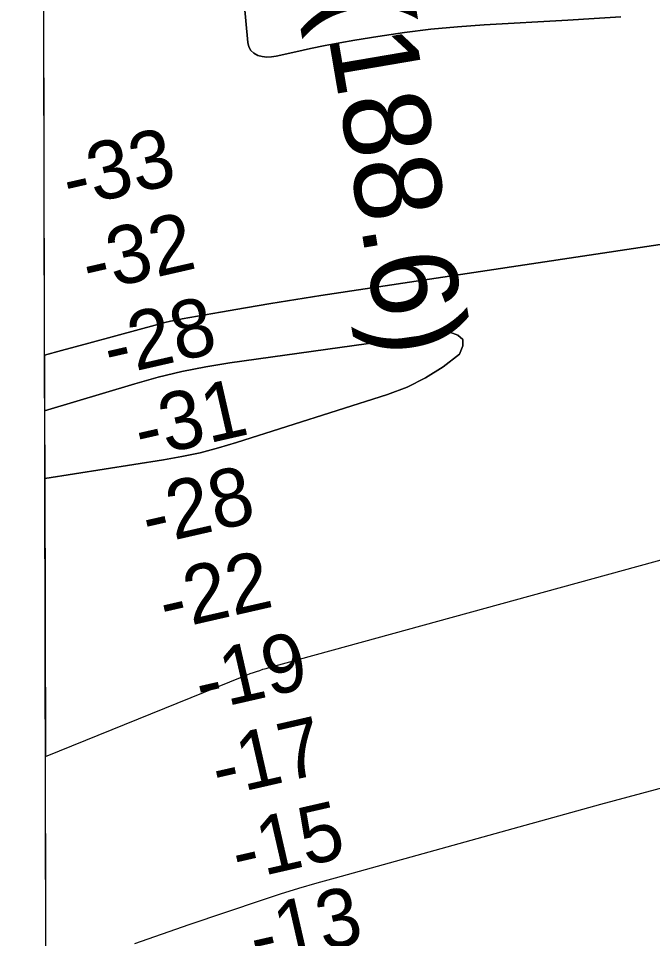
# Model space of a CAD drawing. Extents: x 3355677 to 3393573, y 612928 to 638357.
# Drawn here: x 3359768 to 3360499, y 622036 to 623097 of the extents above; entities that cross this region are included whole.
import ezdxf

# ---------------------------------------------------------------- set-up
doc = ezdxf.new("R2010")
doc.units = 0
for name, color, linetype in [('V-CHAN-NAID', 7, 'Continuous'), ('V-GRID-FRAM', 7, 'Continuous'), ('V-RIVR-RANG', 7, 'Continuous'), ('V-TOPO-DPTH', 7, 'Continuous'), ('V-TOPO-MINR', 7, 'Continuous')]:
    doc.layers.add(name, color=color, linetype=linetype)

msp = doc.modelspace()

# ---------------------------------------------------------------- linework, layer by layer
at = {"layer": 'V-GRID-FRAM'}
msp.add_lwpolyline([(3359767.9, 636495.9), (3391341.6, 636578.5), (3391397.2, 618394.8), (3359807.6, 618312.1), (3359767.9, 636495.9)], dxfattribs=at)
at = {"layer": 'V-TOPO-DPTH'}
for points in [[(3359798, 622708.4), (3359795.6, 623812.8), (3359849.6, 623825), (3359885.2, 623832.8), (3359920.7, 623840.5), (3359956.3, 623848), (3359992, 623855.3), (3360422, 623941.7), (3360433.7, 623944), (3360445.4, 623946.2), (3360457.1, 623948.3), (3360468.8, 623950.4), (3360559.4, 623965.6), (3360616.5, 623975.1), (3360673.6, 623984.5), (3360730.7, 623993.5), (3360787.8, 624002.5), (3361207.2, 624067.1), (3361223.6, 624069.5), (3361240, 624071.9), (3361256.4, 624074), (3361948, 624112.6)], [(3359974.9, 623692), (3360032.3, 623068.8), (3360033.6, 623063.9), (3360035.9, 623059.7), (3360039.4, 623056.6), (3360043.7, 623054.1), (3360049, 623052.8), (3360054.3, 623052), (3360059.6, 623052.2), (3360065, 623053), (3360087.8, 623058.2), (3360104.6, 623061.9), (3360121.5, 623065.4), (3360138.5, 623068.6), (3360155.5, 623071.5), (3360182.3, 623075.8), (3360212.8, 623080.3), (3360243.3, 623084.1), (3360274, 623086.9), (3360304.7, 623089.2), (3360401.2, 623094.7), (3360431.7, 623096.6), (3360462.1, 623098.6)], [(3360462.1, 623098.6), (3360431.7, 623096.6), (3360401.2, 623094.7), (3360304.7, 623089.2), (3360274, 623086.9), (3360243.3, 623084.1), (3360212.8, 623080.3), (3360182.3, 623075.8), (3360155.5, 623071.5), (3360138.5, 623068.6), (3360121.5, 623065.4), (3360104.6, 623061.9), (3360087.8, 623058.2), (3360065, 623053), (3360059.6, 623052.2), (3360054.3, 623052), (3360049, 623052.8), (3360043.7, 623054.1), (3360039.4, 623056.6), (3360035.9, 623059.7), (3360033.6, 623063.9), (3360032.3, 623068.8), (3359974.9, 623692)], [(3360543.2, 622841.4), (3360116.6, 622777.2), (3360087.6, 622772.7), (3360058.7, 622768.1), (3360029.8, 622763.2), (3360000.9, 622758.2), (3359956.8, 622750.3), (3359950, 622749), (3359943.2, 622747.6), (3359936.5, 622746), (3359929.8, 622744.2), (3359880.3, 622730.8), (3359848.9, 622722.2), (3359817.5, 622713.7), (3359798, 622708.4)], [(3360543.2, 622841.4), (3360116.6, 622777.2), (3360087.6, 622772.7), (3360058.7, 622768.1), (3360029.8, 622763.2), (3360000.9, 622758.2), (3359956.8, 622750.3), (3359950, 622749), (3359943.2, 622747.6), (3359936.5, 622746), (3359929.8, 622744.2), (3359880.3, 622730.8), (3359848.9, 622722.2), (3359817.5, 622713.7), (3359798, 622708.4)], [(3359798, 622708.4), (3359798.1, 622644.3), (3359901.9, 622675.6), (3359929, 622683.1), (3359956.3, 622689.7), (3359983.9, 622695.1), (3360011.7, 622699.6), (3360265, 622735), (3360274.4, 622731.7), (3360280.1, 622726.7), (3360280.2, 622719.1), (3360276.5, 622709.8), (3360257.4, 622695.1), (3360237.3, 622682.2), (3360215.9, 622671.8), (3360193.4, 622663.1), (3360019.2, 622607.7), (3359998.4, 622601.6), (3359977.5, 622596.1), (3359956.3, 622591.6), (3359935, 622587.8), (3359798.3, 622566.3), (3359799, 622245.9)], [(3359798.1, 622644.3), (3359798.3, 622566.3), (3359935, 622587.8), (3359956.3, 622591.6), (3359977.5, 622596.1), (3359998.4, 622601.6), (3360019.2, 622607.7), (3360193.4, 622663.1), (3360215.9, 622671.8), (3360237.3, 622682.2), (3360257.4, 622695.1), (3360276.5, 622709.8), (3360280.2, 622719.1), (3360280.1, 622726.7), (3360274.4, 622731.7), (3360265, 622735), (3360011.7, 622699.6), (3359983.9, 622695.1), (3359956.3, 622689.7), (3359929, 622683.1), (3359901.9, 622675.6), (3359798.1, 622644.3)], [(3359800.1, 621714.6), (3359799, 622245.9), (3360027.8, 622338.6), (3360031.4, 622340), (3360035, 622341.4), (3360038.7, 622342.7), (3360042.3, 622344), (3360046, 622345.2), (3360049.7, 622346.4), (3360053.4, 622347.5), (3360057.1, 622348.6), (3360624.8, 622504.4)], [(3359799, 622245.9), (3360027.8, 622338.6), (3360031.4, 622340), (3360035, 622341.4), (3360038.7, 622342.7), (3360042.3, 622344), (3360046, 622345.2), (3360049.7, 622346.4), (3360053.4, 622347.5), (3360057.1, 622348.6), (3360624.8, 622504.4)]]:
    msp.add_lwpolyline(points, dxfattribs=at)
at = {"layer": 'V-TOPO-MINR'}
for points in [[(3360462.1, 623098.6), (3360431.7, 623096.6), (3360401.2, 623094.7), (3360304.7, 623089.2), (3360274, 623086.9), (3360243.3, 623084.1), (3360212.8, 623080.3), (3360182.3, 623075.8), (3360155.5, 623071.5), (3360138.5, 623068.6), (3360121.5, 623065.4), (3360104.6, 623061.9), (3360087.8, 623058.2), (3360065, 623053), (3360059.6, 623052.2), (3360054.3, 623052), (3360049, 623052.8), (3360043.7, 623054.1), (3360039.4, 623056.6), (3360035.9, 623059.7), (3360033.6, 623063.9), (3360032.3, 623068.8), (3359974.9, 623692)], [(3359798, 622708.4), (3359817.5, 622713.7), (3359848.9, 622722.2), (3359880.3, 622730.8), (3359929.8, 622744.2), (3359936.5, 622746), (3359943.2, 622747.6), (3359950, 622749), (3359956.8, 622750.3), (3360000.9, 622758.2), (3360029.8, 622763.2), (3360058.7, 622768.1), (3360087.6, 622772.7), (3360116.6, 622777.2), (3360543.2, 622841.4)], [(3359798.3, 622566.3), (3359935, 622587.8), (3359956.3, 622591.6), (3359977.5, 622596.1), (3359998.4, 622601.6), (3360019.2, 622607.7), (3360193.4, 622663.1), (3360215.9, 622671.8), (3360237.3, 622682.2), (3360257.4, 622695.1), (3360276.5, 622709.8), (3360280.2, 622719.1), (3360280.1, 622726.7), (3360274.4, 622731.7), (3360265, 622735), (3360011.7, 622699.6), (3359983.9, 622695.1), (3359956.3, 622689.7), (3359929, 622683.1), (3359901.9, 622675.6), (3359798.1, 622644.3)], [(3359799, 622245.9), (3360027.8, 622338.6), (3360031.4, 622340), (3360035, 622341.4), (3360038.7, 622342.7), (3360042.3, 622344), (3360046, 622345.2), (3360049.7, 622346.4), (3360053.4, 622347.5), (3360057.1, 622348.6), (3360624.8, 622504.4)], [(3359902.2, 622030.5), (3359964.9, 622052.4), (3360049.2, 622080.6), (3360070.1, 622087.4), (3360091.1, 622094), (3360112.2, 622100.2), (3360133.3, 622106.2), (3360439.2, 622190.9), (3360486.4, 622203.7), (3360533.6, 622216.4)]]:
    msp.add_lwpolyline(points, dxfattribs=at)

# ---------------------------------------------------------------- texts
at = {"layer": 'V-CHAN-NAID'}
msp.add_text('RESCUE "190" (188.6)', height=100, rotation=279.6705, dxfattribs=at).set_placement((3359957.9, 624057.1))
at = {"layer": 'V-RIVR-RANG'}
for s, p in [('-33', (3359826.5, 622877.8)), ('-32', (3359849.1, 622780.4)), ('-28', (3359873.7, 622683.4)), ('-31', (3359909.4, 622589)), ('-28', (3359917.8, 622488.4)), ('-22', (3359937.8, 622390.3)), ('-19', (3359979.2, 622297.2)), ('-17', (3359998.4, 622199)), ('-15', (3360021.5, 622101.7)), ('-13', (3360042, 622003.8))]:
    msp.add_text(s, height=67, rotation=12.8825, dxfattribs=at).set_placement(p)

doc.saveas('drawing.dxf')
